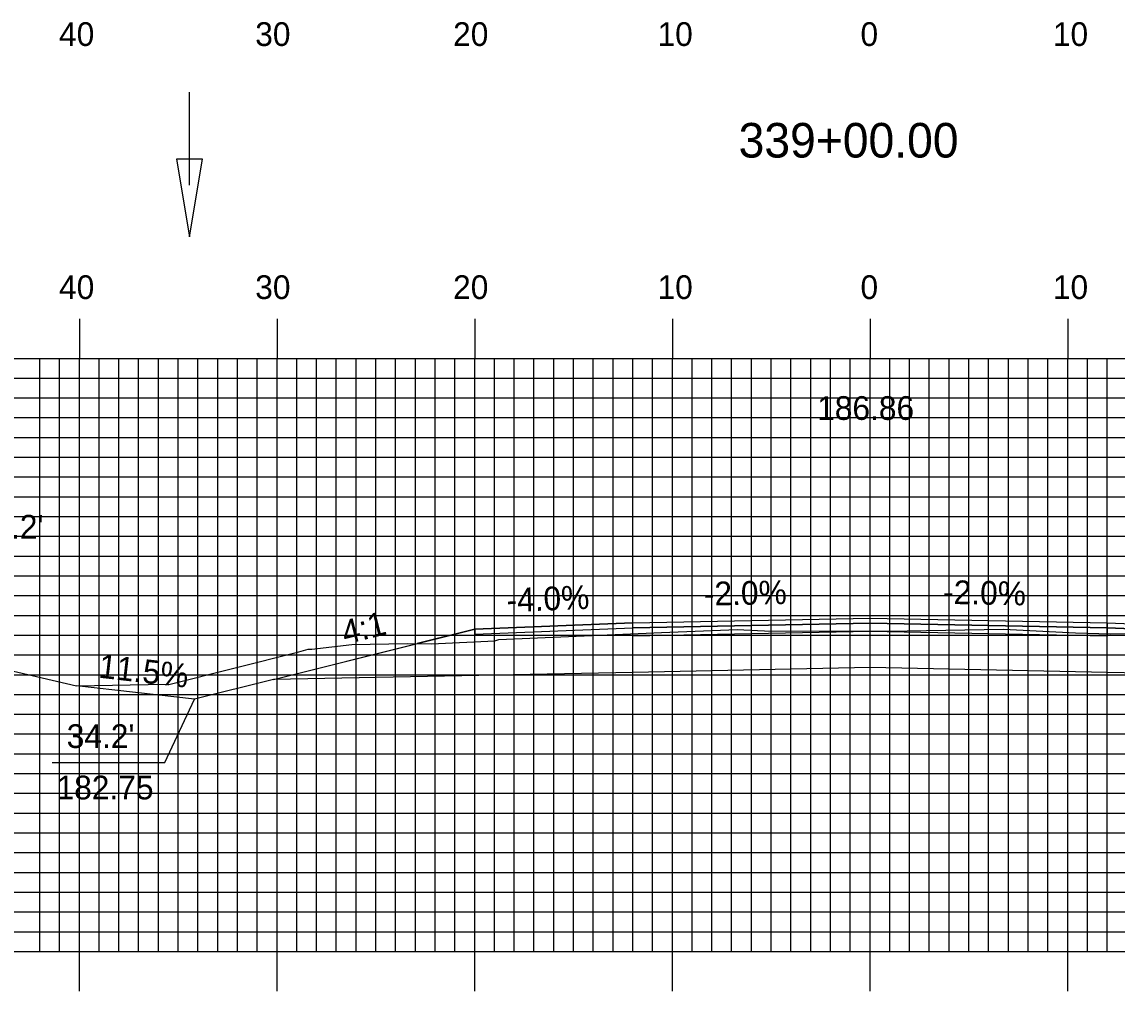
# Model space of a CAD drawing. Extents: x 1823966 to 1824309, y 442591 to 442811.
# Drawn here: x 1824088.9 to 1824144.3, y 442694.6 to 442743.6 of the extents above; entities that cross this region are included whole.
import ezdxf

# ---------------------------------------------------------------- set-up
doc = ezdxf.new("R2010")
doc.units = 0
for name, color, linetype in [('ANNOTATION', 7, 'Continuous'), ('D_Drainage_Ditch_Line', 7, 'Continuous'), ('D_Roadway_Centerline', 7, 'Continuous'), ('D_Roadway_Centerline_Text', 7, 'Continuous'), ('D_Roadway_Edge_Shoulder', 7, 'Continuous'), ('D_Roadway_Edge_TW', 7, 'Continuous'), ('D_Roadway_Pavement', 7, 'Continuous'), ('D_Roadway_SlopeLines', 7, 'Continuous'), ('D_Roadway_SubGrade', 7, 'Continuous'), ('D_Text_Standard', 7, 'Continuous'), ('H_V ANNOTATION', 7, 'Continuous'), ('MAJOR', 7, 'Continuous'), ('MINOR', 7, 'Continuous'), ('S_Roadway_Centerline', 7, 'Continuous')]:
    doc.layers.add(name, color=color, linetype=linetype)

msp = doc.modelspace()

# ---------------------------------------------------------------- linework, layer by layer
at = {"layer": 'ANNOTATION'}
msp.add_lwpolyline([(1824090.447, 442706.153), (1824096.139, 442706.153), (1824097.648, 442709.342)], dxfattribs=at)
at = {"layer": 'D_Drainage_Ditch_Line'}
msp.add_line((1824097.399, 442735.356), (1824097.398, 442740.055), dxfattribs=at)
msp.add_lwpolyline([(1824098.055, 442736.668), (1824096.742, 442736.668), (1824097.399, 442732.731)], close=True, dxfattribs=at)
at = {"layer": 'D_Roadway_Centerline'}
msp.add_lwpolyline([(1824101.648, 442710.342), (1824108.91, 442712.157), (1824111.822, 442712.885), (1824119.822, 442713.205), (1824131.822, 442713.445), (1824143.822, 442713.205), (1824151.822, 442712.885), (1824161.996, 442710.342), (1824165.996, 442709.342), (1824177.386, 442715.037), (1824178.636, 442715.596), (1824179.886, 442716.022), (1824181.136, 442716.317), (1824182.386, 442716.479)], dxfattribs=at)
at = {"layer": 'D_Roadway_Edge_Shoulder'}
for points in [[(1824119.822, 442713.205), (1824111.822, 442712.885), (1824111.822, 442712.635), (1824119.822, 442712.955)], [(1824143.822, 442713.205), (1824151.822, 442712.885), (1824151.822, 442712.635), (1824143.822, 442712.955)]]:
    msp.add_lwpolyline(points, close=True, dxfattribs=at)
at = {"layer": 'D_Roadway_Edge_TW'}
msp.add_lwpolyline([(1824119.822, 442712.955), (1824119.822, 442713.205), (1824131.822, 442713.445), (1824143.822, 442713.205), (1824143.822, 442712.955), (1824131.822, 442713.195)], close=True, dxfattribs=at)
at = {"layer": 'D_Roadway_Pavement'}
msp.add_lwpolyline([(1824119.822, 442712.538), (1824119.822, 442712.955), (1824131.822, 442713.195), (1824143.822, 442712.955), (1824143.822, 442712.538), (1824131.822, 442712.778)], close=True, dxfattribs=at)
at = {"layer": 'D_Roadway_SlopeLines'}
for p, q in [((1824101.648, 442710.342), (1824097.648, 442709.342)), ((1824097.648, 442709.342), (1824091.671, 442710.03))]:
    msp.add_line(p, q, dxfattribs=at)
msp.add_lwpolyline([(1824111.822, 442712.885), (1824108.91, 442712.157)], dxfattribs=at)
at = {"layer": 'D_Roadway_SubGrade'}
msp.add_lwpolyline([(1824119.822, 442710.705), (1824101.648, 442710.342), (1824111.822, 442712.885), (1824111.822, 442712.635), (1824119.822, 442712.955), (1824131.822, 442713.195), (1824143.822, 442712.955), (1824151.822, 442712.635), (1824151.822, 442712.885), (1824161.996, 442710.342), (1824143.822, 442710.705), (1824131.822, 442710.945)], close=True, dxfattribs=at)
at = {"layer": 'MAJOR'}
for p, q in [((1824091.822, 442728.592), (1824091.822, 442726.588)), ((1824101.822, 442728.592), (1824101.822, 442726.588)), ((1824111.822, 442728.592), (1824111.822, 442726.588)), ((1824121.822, 442728.592), (1824121.822, 442726.588)), ((1824131.822, 442728.592), (1824131.822, 442726.588)), ((1824141.822, 442728.592), (1824141.822, 442726.588)), ((1823991.822, 442726.588), (1824271.822, 442726.588)), ((1823991.822, 442726.588), (1824271.822, 442726.588)), ((1824091.822, 442696.588), (1824091.822, 442726.588)), ((1824101.822, 442696.588), (1824101.822, 442726.588)), ((1824111.822, 442696.588), (1824111.822, 442726.588)), ((1824121.822, 442696.588), (1824121.822, 442726.588)), ((1824131.822, 442696.588), (1824131.822, 442726.588)), ((1824141.822, 442696.588), (1824141.822, 442726.588)), ((1823991.822, 442721.588), (1824271.822, 442721.588)), ((1823991.822, 442716.588), (1824271.822, 442716.588)), ((1823991.822, 442711.588), (1824271.822, 442711.588)), ((1823991.822, 442706.588), (1824271.822, 442706.588)), ((1823991.822, 442701.588), (1824271.822, 442701.588)), ((1823991.822, 442696.588), (1824271.822, 442696.588)), ((1823991.822, 442696.588), (1824271.822, 442696.588)), ((1824091.822, 442694.584), (1824091.822, 442696.588)), ((1824101.822, 442694.584), (1824101.822, 442696.588)), ((1824111.822, 442694.584), (1824111.822, 442696.588)), ((1824121.822, 442694.584), (1824121.822, 442696.588)), ((1824131.822, 442694.584), (1824131.822, 442696.588)), ((1824141.822, 442694.584), (1824141.822, 442696.588))]:
    msp.add_line(p, q, dxfattribs=at)
at = {"layer": 'MINOR'}
for p, q in [((1824089.822, 442696.588), (1824089.822, 442726.588)), ((1824090.822, 442696.588), (1824090.822, 442726.588)), ((1824092.822, 442696.588), (1824092.822, 442726.588)), ((1824093.822, 442696.588), (1824093.822, 442726.588)), ((1824094.822, 442696.588), (1824094.822, 442726.588)), ((1824095.822, 442696.588), (1824095.822, 442726.588)), ((1824096.822, 442696.588), (1824096.822, 442726.588)), ((1824097.822, 442696.588), (1824097.822, 442726.588)), ((1824098.822, 442696.588), (1824098.822, 442726.588)), ((1824099.822, 442696.588), (1824099.822, 442726.588)), ((1824100.822, 442696.588), (1824100.822, 442726.588)), ((1824102.822, 442696.588), (1824102.822, 442726.588)), ((1824103.822, 442696.588), (1824103.822, 442726.588)), ((1824104.822, 442696.588), (1824104.822, 442726.588)), ((1824105.822, 442696.588), (1824105.822, 442726.588)), ((1824106.822, 442696.588), (1824106.822, 442726.588)), ((1824107.822, 442696.588), (1824107.822, 442726.588)), ((1824108.822, 442696.588), (1824108.822, 442726.588)), ((1824109.822, 442696.588), (1824109.822, 442726.588)), ((1824110.822, 442696.588), (1824110.822, 442726.588)), ((1824112.822, 442696.588), (1824112.822, 442726.588)), ((1824113.822, 442696.588), (1824113.822, 442726.588)), ((1824114.822, 442696.588), (1824114.822, 442726.588)), ((1824115.822, 442696.588), (1824115.822, 442726.588)), ((1824116.822, 442696.588), (1824116.822, 442726.588)), ((1824117.822, 442696.588), (1824117.822, 442726.588)), ((1824118.822, 442696.588), (1824118.822, 442726.588)), ((1824119.822, 442696.588), (1824119.822, 442726.588)), ((1824120.822, 442696.588), (1824120.822, 442726.588)), ((1824122.822, 442696.588), (1824122.822, 442726.588)), ((1824123.822, 442696.588), (1824123.822, 442726.588)), ((1824124.822, 442696.588), (1824124.822, 442726.588)), ((1824125.822, 442696.588), (1824125.822, 442726.588)), ((1824126.822, 442696.588), (1824126.822, 442726.588)), ((1824127.822, 442696.588), (1824127.822, 442726.588)), ((1824128.822, 442696.588), (1824128.822, 442726.588)), ((1824129.822, 442696.588), (1824129.822, 442726.588)), ((1824130.822, 442696.588), (1824130.822, 442726.588)), ((1824132.822, 442696.588), (1824132.822, 442726.588)), ((1824133.822, 442696.588), (1824133.822, 442726.588)), ((1824134.822, 442696.588), (1824134.822, 442726.588)), ((1824135.822, 442696.588), (1824135.822, 442726.588)), ((1824136.822, 442696.588), (1824136.822, 442726.588)), ((1824137.822, 442696.588), (1824137.822, 442726.588)), ((1824138.822, 442696.588), (1824138.822, 442726.588)), ((1824139.822, 442696.588), (1824139.822, 442726.588)), ((1824140.822, 442696.588), (1824140.822, 442726.588)), ((1824142.822, 442696.588), (1824142.822, 442726.588)), ((1824143.822, 442696.588), (1824143.822, 442726.588)), ((1823991.822, 442725.588), (1824271.822, 442725.588)), ((1823991.822, 442724.588), (1824271.822, 442724.588)), ((1823991.822, 442723.588), (1824271.822, 442723.588)), ((1823991.822, 442722.588), (1824271.822, 442722.588)), ((1823991.822, 442720.588), (1824271.822, 442720.588)), ((1823991.822, 442719.588), (1824271.822, 442719.588)), ((1823991.822, 442718.588), (1824271.822, 442718.588)), ((1823991.822, 442717.588), (1824271.822, 442717.588)), ((1823991.822, 442715.588), (1824271.822, 442715.588)), ((1823991.822, 442714.588), (1824271.822, 442714.588)), ((1823991.822, 442713.588), (1824271.822, 442713.588)), ((1823991.822, 442712.588), (1824271.822, 442712.588)), ((1823991.822, 442710.588), (1824271.822, 442710.588)), ((1823991.822, 442709.588), (1824271.822, 442709.588)), ((1823991.822, 442708.588), (1824271.822, 442708.588)), ((1823991.822, 442707.588), (1824271.822, 442707.588)), ((1823991.822, 442705.588), (1824271.822, 442705.588)), ((1823991.822, 442704.588), (1824271.822, 442704.588)), ((1823991.822, 442703.588), (1824271.822, 442703.588)), ((1823991.822, 442702.588), (1824271.822, 442702.588)), ((1823991.822, 442700.588), (1824271.822, 442700.588)), ((1823991.822, 442699.588), (1824271.822, 442699.588)), ((1823991.822, 442698.588), (1824271.822, 442698.588)), ((1823991.822, 442697.588), (1824271.822, 442697.588))]:
    msp.add_line(p, q, dxfattribs=at)
at = {"layer": 'S_Roadway_Centerline'}
msp.add_lwpolyline([(1824086.957, 442711.122), (1824091.671, 442710.03), (1824096.208, 442710.114), (1824096.319, 442710.096), (1824096.347, 442710.099), (1824102.933, 442711.742), (1824103.406, 442711.883), (1824103.579, 442711.883), (1824105.611, 442712.107), (1824108.409, 442712.16), (1824109.637, 442712.153), (1824112.844, 442712.301), (1824113.052, 442712.363), (1824121.28, 442712.72), (1824125.094, 442712.872), (1824126.826, 442712.787), (1824133.698, 442712.805), (1824138.579, 442712.895), (1824142.218, 442712.704), (1824143.98, 442712.654), (1824145.907, 442712.678)], dxfattribs=at)

# ---------------------------------------------------------------- texts
at = {"layer": 'ANNOTATION'}
for s, rotation, p in [('-2.0%', 1.1458, (1824123.428, 442714.078)), ('-2.0%', 358.8542, (1824135.508, 442714.172)), ('-4.0%', 2.2906, (1824113.454, 442713.752)), ('4:1', 14.0362, (1824105.27, 442712.109)), ('11.5%', 353.4316, (1824092.754, 442710.443))]:
    msp.add_text(s, height=1.2, rotation=rotation, dxfattribs=at).set_placement(p)
for s, p in [("34.2'", (1824091.182, 442706.88)), ('182.75', (1824090.668, 442704.28))]:
    msp.add_text(s, height=1.2, dxfattribs=at).set_placement(p)
at = {"layer": 'D_Roadway_Centerline'}
for s, p in [('C', (1824131.817, 442713.445)), ('L', (1824131.822, 442713.438))]:
    msp.add_text(s, height=0.0146, dxfattribs=at).set_placement(p)
at = {"layer": 'D_Roadway_Centerline_Text'}
msp.add_text('186.86', height=1.2, dxfattribs=at).set_placement((1824129.146, 442723.475))
at = {"layer": 'D_Text_Standard'}
msp.add_text("40.2'", height=1.2, dxfattribs=at).set_placement((1824086.579, 442717.471))
at = {"layer": 'H_V ANNOTATION'}
for s, height, p in [('40', 1.2, (1824090.794, 442742.388)), ('30', 1.2, (1824100.719, 442742.388)), ('20', 1.2, (1824110.73, 442742.388)), ('10', 1.2, (1824121.072, 442742.388)), ('0', 1.2, (1824131.34, 442742.388)), ('10', 1.2, (1824141.072, 442742.388)), ('339+00.00', 1.75, (1824125.174, 442736.744)), ('40', 1.2, (1824090.794, 442729.588)), ('30', 1.2, (1824100.719, 442729.588)), ('20', 1.2, (1824110.73, 442729.588)), ('10', 1.2, (1824121.072, 442729.588)), ('0', 1.2, (1824131.34, 442729.588)), ('10', 1.2, (1824141.072, 442729.588))]:
    msp.add_text(s, height=height, dxfattribs=at).set_placement(p)
at = {"layer": 'S_Roadway_Centerline'}
for s, p in [('L', (1824125.086, 442712.864)), ('C', (1824125.089, 442712.872))]:
    msp.add_text(s, height=0.0146, dxfattribs=at).set_placement(p)

doc.saveas('drawing.dxf')
